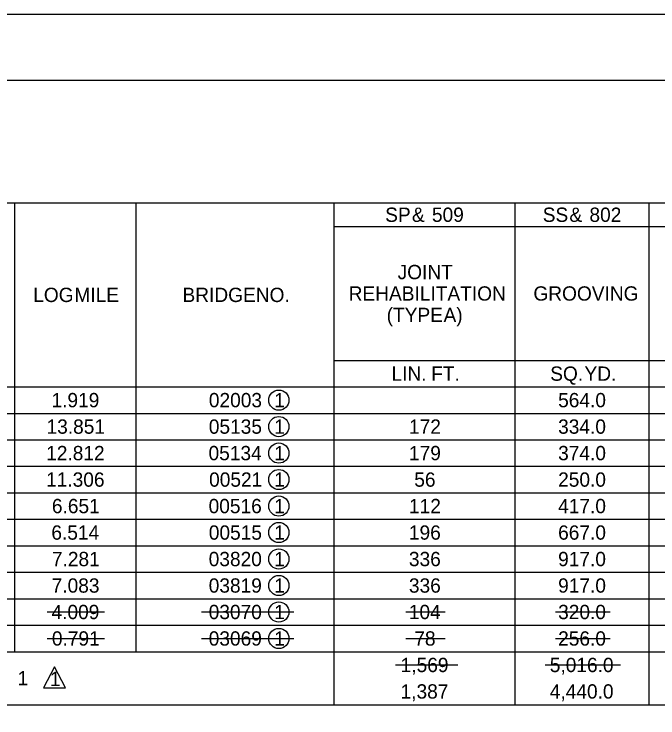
# Model space of a CAD drawing. Extents: x 18 to 14744716, y -5 to 1829144.
# Drawn here: x 24.77 to 30.4, y 10.48 to 16.63 of the extents above; entities that cross this region are included whole.
import ezdxf

# ---------------------------------------------------------------- set-up
doc = ezdxf.new("R2010")
doc.units = 0
for name, color, linetype in [('B_Dimensions', 7, 'Continuous'), ('B_Text', 7, 'Continuous'), ('R_Border', 7, 'Continuous'), ('R_No Plot', 7, 'Continuous')]:
    doc.layers.add(name, color=color, linetype=linetype)

msp = doc.modelspace()

# ---------------------------------------------------------------- linework, layer by layer
at = {"layer": 'B_Dimensions'}
for p, q in [((25.0623, 11.4082), (25.5645, 11.4082)), ((26.4118, 11.4082), (27.2158, 11.4082)), ((28.1944, 11.4082), (28.5374, 11.4082)), ((29.5026, 11.4082), (29.9786, 11.4082)), ((25.0623, 11.177), (25.5645, 11.177)), ((26.4118, 11.177), (27.2158, 11.177)), ((28.1944, 11.177), (28.5374, 11.177)), ((29.5026, 11.177), (29.9786, 11.177)), ((28.1059, 10.9458), (28.6481, 10.9458)), ((29.4124, 10.9458), (30.068, 10.9458)), ((25.1271, 10.9308), (25.0307, 10.7469)), ((25.2236, 10.7469), (25.1271, 10.9308)), ((25.0307, 10.7469), (25.2236, 10.7469))]:
    msp.add_line(p, q, dxfattribs=at)
for centre in [(27.0867, 13.2577), (27.0867, 13.0265), (27.0867, 12.7953), (27.0867, 12.5641), (27.0867, 12.3329), (27.0867, 12.1017), (27.0867, 11.8705), (27.0867, 11.6393), (27.0867, 11.4082), (27.0867, 11.177)]:
    msp.add_circle(centre, 0.0881, dxfattribs=at)
at = {"layer": 'B_Text'}
for p, q in [((19.3916, 14.9795), (51.1014, 14.9795)), ((24.782, 11.0614), (24.782, 14.9795)), ((25.8407, 11.0614), (25.8407, 14.9795)), ((27.5685, 10.599), (27.5685, 14.9795)), ((29.1504, 10.599), (29.1504, 14.9795)), ((30.3185, 10.599), (30.3185, 14.9795)), ((27.5685, 14.7726), (51.1014, 14.7726)), ((27.5685, 13.6045), (51.1014, 13.6045)), ((19.3916, 13.3733), (51.1014, 13.3733)), ((20.3042, 13.1421), (51.1014, 13.1421)), ((20.3042, 12.9109), (51.1014, 12.9109)), ((20.3042, 12.6797), (51.1014, 12.6797)), ((20.3042, 12.4485), (51.1014, 12.4485)), ((20.3042, 12.2173), (51.1014, 12.2173)), ((20.3042, 11.9861), (51.1014, 11.9861)), ((20.3042, 11.7549), (51.1014, 11.7549)), ((20.3042, 11.5238), (51.1014, 11.5238)), ((20.3042, 11.2926), (51.1014, 11.2926)), ((20.3042, 11.0614), (51.1014, 11.0614)), ((19.3916, 10.599), (51.1014, 10.599))]:
    msp.add_line(p, q, dxfattribs=at)
at = {"layer": 'R_Border'}
msp.add_line((19.2929, 16.0508), (51.2001, 16.0508), dxfattribs=at)
at = {"layer": 'R_No Plot'}
msp.add_lwpolyline([(17.7769, 16.6276), (51.7769, 16.6276), (51.7769, -5.3724), (17.7769, -5.3724)], close=True, dxfattribs=at)

# ---------------------------------------------------------------- texts
at = {"layer": 'B_Text'}
for s, p in [('SP', (28.0148, 14.8136)), (' &', (28.2019, 14.8136)), (' 509', (28.3766, 14.8136)), ('SS', (29.3902, 14.8136)), (' &', (29.577, 14.8136)), (' 802', (29.7517, 14.8136)), ('JOINT', (28.1235, 14.3133)), ('LOG', (24.9418, 14.114)), (' MILE', (25.255, 14.114)), ('BRIDGE', (26.2451, 14.114)), (' NO.', (26.8385, 14.114)), ('REHABILITATION', (27.6959, 14.1261)), ('GROOVING', (29.3087, 14.1261)), ('(TYPE', (28.0277, 13.9389)), (' A)', (28.4779, 13.9389)), ('LIN.', (28.0699, 13.4265)), (' FT.', (28.3697, 13.4265)), ('SQ.', (29.4555, 13.4265)), (' YD.', (29.7085, 13.4265)), ('1.919', (25.1016, 13.1953)), ('02003', (26.4753, 13.1953)), ('1', (27.0468, 13.1953)), ('564.0', (29.5246, 13.1953)), ('13.851', (25.0582, 12.9641)), ('05135', (26.4749, 12.9641)), ('1', (27.0468, 12.9641)), ('172', (28.2227, 12.9641)), ('334.0', (29.5246, 12.9641)), ('12.812', (25.055, 12.7329)), ('05134', (26.4726, 12.7329)), ('1', (27.0468, 12.7329)), ('179', (28.2225, 12.7329)), ('374.0', (29.5246, 12.7329)), ('11.306', (25.0541, 12.5017)), ('00521', (26.4774, 12.5017)), ('1', (27.0468, 12.5017)), ('56', (28.2686, 12.5017)), ('250.0', (29.5246, 12.5017)), ('6.651', (25.105, 12.2705)), ('00516', (26.4733, 12.2705)), ('1', (27.0468, 12.2705)), ('112', (28.2227, 12.2705)), ('417.0', (29.5246, 12.2705)), ('6.514', (25.1002, 12.0393)), ('00515', (26.4749, 12.0393)), ('196', (28.2218, 12.0393)), ('667.0', (29.5246, 12.0393)), ('1', (27.0468, 12.0393)), ('7.281', (25.105, 11.8081)), ('03820', (26.4739, 11.8081)), ('1', (27.0468, 11.8081)), ('336', (28.2218, 11.8081)), ('917.0', (29.5246, 11.8081)), ('7.083', (25.1029, 11.5769)), ('03819', (26.474, 11.5769)), ('1', (27.0468, 11.5769)), ('336', (28.2218, 11.5769)), ('917.0', (29.5246, 11.5769)), ('4.009', (25.1016, 11.3458)), ('03070', (26.4739, 11.3458)), ('1', (27.0468, 11.3458)), ('104', (28.2211, 11.3458)), ('320.0', (29.5246, 11.3458)), ('0.791', (25.105, 11.1146)), ('03069', (26.474, 11.1146)), ('1', (27.0468, 11.1146)), ('78', (28.2689, 11.1146)), ('256.0', (29.5246, 11.1146)), ('1,569', (28.1497, 10.8834)), ('5,016.0', (29.4517, 10.8834)), (' 1', (24.7591, 10.7678)), ('1', (25.0872, 10.7615)), ('1,387', (28.1492, 10.6522)), ('4,440.0', (29.4517, 10.6522))]:
    msp.add_text(s, height=0.1248, dxfattribs=at).set_placement(p)

doc.saveas('drawing.dxf')
